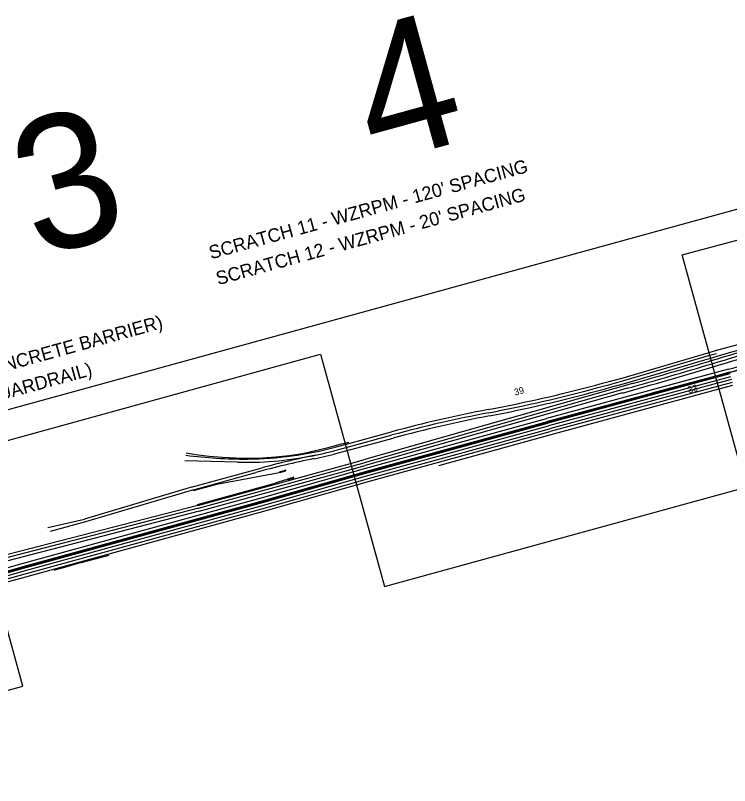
# Model space of a CAD drawing. Extents: x 2129512 to 2138277, y 657615 to 661243.
# Drawn here: x 2132183 to 2134849, y 657615 to 660491 of the extents above; entities that cross this region are included whole.
import ezdxf

# ---------------------------------------------------------------- set-up
doc = ezdxf.new("R2010")
doc.units = 0
for name, color, linetype in [('GE_X_Alignment_100_Stations', 7, 'Continuous'), ('MT_P_CL_50', 7, 'Continuous'), ('MT_P_Dotted_Line', 7, 'Continuous'), ('MT_P_Gore_Marking', 7, 'Continuous'), ('MT_P_PCB', 7, 'Continuous'), ('MT_P_Temp_Road', 7, 'Continuous'), ('MT_P_Traffic_Attenuator', 7, 'Continuous'), ('MT_P_Work_Area', 7, 'Continuous'), ('MT_X_Dotted_Line', 7, 'Continuous'), ('MT_X_Drums', 7, 'Continuous'), ('MT_X_Gore_Marking', 7, 'Continuous'), ('MT_X_Traffic_Attenuator', 7, 'Continuous'), ('PV_P_Shoulder', 7, 'Continuous'), ('SC_Scratch1', 7, 'Continuous')]:
    doc.layers.add(name, color=color, linetype=linetype)

msp = doc.modelspace()

# ---------------------------------------------------------------- linework, layer by layer
at = {"layer": 'GE_X_Alignment_100_Stations'}
for p, q in [((2134796.6, 659239.6), (2135219, 659355.8)), ((2134451.1, 659138.2), (2134772.2, 659232.4)), ((2134772.2, 659232.4), (2134796.6, 659239.6)), ((2134399, 659123.9), (2134451.1, 659138.2))]:
    msp.add_line(p, q, dxfattribs=at)
msp.add_arc((2132878.5, 664648.1), 5729.6, 281.30004, 285.38861, dxfattribs=at)
at = {"layer": 'MT_P_CL_50'}
for p, q in [((2134456.9, 659117), (2134778.1, 659211.2)), ((2134778.1, 659211.2), (2134802.4, 659218.3)), ((2134855.4, 659131.3), (2134803.9, 659117.4)), ((2134803.9, 659117.4), (2134176.4, 658947.7)), ((2134806.8, 659106.8), (2134179.4, 658937.1)), ((2134858.3, 659120.7), (2134806.8, 659106.8)), ((2133501.5, 658761.9), (2134176.4, 658947.7)), ((2133504.4, 658751.3), (2134179.4, 658937.1)), ((2133453.4, 658748.3), (2133501.5, 658761.9)), ((2133116.7, 658652.7), (2133453.4, 658748.3)), ((2132219.5, 658405.8), (2133116.7, 658652.7))]:
    msp.add_line(p, q, dxfattribs=at)
at = {"layer": 'MT_P_Dotted_Line'}
for p, q in [((2134793.3, 659155.9), (2134555.2, 659091.6)), ((2134844.8, 659169.9), (2134793.3, 659155.9)), ((2134847.9, 659158.3), (2134796.5, 659144.4)), ((2134796.5, 659144.4), (2134558.4, 659080)), ((2132863.9, 658661.3), (2133434.2, 658818.3)), ((2133434.2, 658818.3), (2133482.4, 658831.5)), ((2133437.1, 658807.6), (2133485.4, 658820.9)), ((2133440, 658797), (2133488.4, 658810.4)), ((2132866.7, 658650.7), (2133437.1, 658807.6)), ((2132869.6, 658640), (2133440, 658797)), ((2132863.9, 658661.3), (2132080.8, 658459.6)), ((2132866.7, 658650.7), (2132083.8, 658448.9)), ((2132869.6, 658640), (2132086.9, 658437.4))]:
    msp.add_line(p, q, dxfattribs=at)
for radius, start in [(2286, 285.1339), (2298, 285.1338)]:
    msp.add_arc((2134248, 661376.6), radius, start, 291.781, dxfattribs=at)
at = {"layer": 'MT_P_Gore_Marking'}
for p, q in [((2133413.3, 658894.2), (2133427.3, 658897.8)), ((2132935.2, 658741), (2133161.2, 658783.4)), ((2133161.2, 658783.4), (2133170.9, 658786)), ((2133191.1, 658756.8), (2133152.6, 658743.9)), ((2133191.1, 658756.8), (2133200.7, 658759.4)), ((2132848.4, 658717.1), (2132935.2, 658741)), ((2132863.1, 658664.2), (2133152.6, 658743.9)), ((2132429.1, 658447.5), (2132533.2, 658476.1))]:
    msp.add_line(p, q, dxfattribs=at)
for points in [[(2132820.8, 658857.2), (2132856.8, 658851.4), (2132907.1, 658845.2), (2132956.8, 658841), (2133006, 658838.4), (2133060.1, 658838.1), (2133105.4, 658839.2), (2133155.2, 658842.8), (2133204.8, 658847.5), (2133254.8, 658855.7), (2133303.6, 658866.6), (2133350.5, 658877.8), (2133400.2, 658890.8), (2133413.3, 658894.2)], [(2132429.1, 658447.5), (2132366.6, 658429.8), (2132329.4, 658418.9), (2132327.6, 658418.7)]]:
    msp.add_lwpolyline(points, dxfattribs=at)
at = {"layer": 'MT_P_PCB'}
for p, q in [((2134793.3, 659155.9), (2134165.8, 658986.2)), ((2134844.8, 659169.9), (2134793.3, 659155.9)), ((2134847.9, 659158.3), (2134796.5, 659144.4)), ((2134796.5, 659144.4), (2134169, 658974.7)), ((2134798.1, 659138.6), (2134170.6, 658968.9)), ((2134849.5, 659152.5), (2134798.1, 659138.6)), ((2134486.3, 659116.4), (2133482.4, 658831.5)), ((2134182.5, 658925.5), (2134809.8, 659096.1)), ((2134809.8, 659096.1), (2134861.2, 659110.1)), ((2134449.7, 659081.1), (2133488.4, 658810.4)), ((2133490.9, 658800.5), (2134165.8, 658986.2)), ((2133494.1, 658788.9), (2134169, 658974.7)), ((2133495.7, 658783.1), (2134170.6, 658968.9)), ((2133414.6, 658889.2), (2133586.7, 658936)), ((2133764.1, 658810.3), (2134182.5, 658925.5)), ((2133421, 658866.1), (2133593, 658912.8)), ((2133377.3, 658879.1), (2133414.6, 658889.2)), ((2133383.6, 658855.9), (2133421, 658866.1)), ((2133011.8, 658822.7), (2132815.6, 658827.2)), ((2132863.9, 658661.3), (2133434.2, 658818.3)), ((2133434.2, 658818.3), (2133482.4, 658831.5)), ((2133440, 658797), (2133488.4, 658810.4)), ((2132844.6, 658730.6), (2133104.1, 658802)), ((2132847.6, 658720), (2133080.6, 658784.1)), ((2132869.6, 658640), (2133440, 658797)), ((2133106.1, 658691.3), (2133442.8, 658786.8)), ((2133442.8, 658786.8), (2133490.9, 658800.5)), ((2133446, 658775.3), (2133494.1, 658788.9)), ((2133447.6, 658769.5), (2133495.7, 658783.1)), ((2133109.3, 658679.7), (2133446, 658775.3)), ((2133110.9, 658674), (2133447.6, 658769.5)), ((2133456.3, 658737.7), (2133504.4, 658751.3)), ((2132844.6, 658730.6), (2132441.7, 658610)), ((2133119.6, 658642.1), (2133456.3, 658737.7)), ((2132847.6, 658720), (2132444.9, 658599.5)), ((2132208.9, 658444.4), (2133106.1, 658691.3)), ((2132212, 658432.8), (2133109.3, 658679.7)), ((2132213.6, 658427), (2133110.9, 658674)), ((2132863.9, 658661.3), (2132080.8, 658459.6)), ((2132869.6, 658640), (2132086.9, 658437.4)), ((2132222.4, 658395.2), (2133119.6, 658642.1)), ((2132304.3, 658578.4), (2132441.7, 658610)), ((2132444.9, 658599.5), (2132312.6, 658564.1)), ((2132093.8, 658412.5), (2132208.9, 658444.4)), ((2132097, 658400.9), (2132212, 658432.8)), ((2132098.6, 658395.2), (2132213.6, 658427)), ((2132107.3, 658363.3), (2132222.4, 658395.2))]:
    msp.add_line(p, q, dxfattribs=at)
for centre, radius, start, end in [((2128236.9, 681140.9), 22918, 286.60693, 287.56698), ((2134248, 661376.6), 2286, 285.1339, 291.781), ((2134248, 661376.6), 2298, 285.1338, 291.781), ((2128236.9, 681140.9), 22918, 285.72897, 286.60693), ((2134842.9, 654308.7), 4794.7, 100.7572, 105.1883), ((2132878.5, 664648.1), 5729.6, 280.75722, 281.2999), ((2134842.9, 654308.7), 4770.7, 100.7572, 105.1883), ((2132878.5, 664648.1), 5753.6, 280.75722, 281.2999), ((2133041.6, 660115.8), 1281.5, 270.3665, 285.1883), ((2133039, 660522.9), 1688.5, 262.5293, 270.3665), ((2133041.6, 660115.8), 1305.5, 281.3395, 285.1883), ((2133041.6, 660115.8), 1293.5, 268.6795, 272.3466), ((2133921, 655730.4), 3167.3, 101.3395, 105.3886)]:
    msp.add_arc(centre, radius, start, end, dxfattribs=at)
at = {"layer": 'MT_P_Temp_Road'}
for p, q in [((2134848.7, 659155.4), (2134797.3, 659141.5)), ((2134797.3, 659141.5), (2134169.8, 658971.8)), ((2133494.9, 658786), (2134169.8, 658971.8)), ((2132935.2, 658741), (2133161.2, 658783.4)), ((2133161.2, 658783.4), (2133170.9, 658786)), ((2133446.8, 658772.4), (2133494.9, 658786)), ((2133110.1, 658676.8), (2133446.8, 658772.4)), ((2133191.1, 658756.8), (2133152.6, 658743.9)), ((2133191.1, 658756.8), (2133200.7, 658759.4)), ((2132848.4, 658717.1), (2132935.2, 658741)), ((2132863.1, 658664.2), (2133152.6, 658743.9)), ((2132212.8, 658429.9), (2133110.1, 658676.8)), ((2132097.8, 658398), (2132212.8, 658429.9))]:
    msp.add_line(p, q, dxfattribs=at)
at = {"layer": 'MT_P_Work_Area'}
for p, q in [((2134802.4, 659218.3), (2135222, 659345.2)), ((2134454, 659127.6), (2134775.2, 659221.8)), ((2134775.2, 659221.8), (2134799.5, 659228.9)), ((2134801, 659128), (2134173.5, 658958.3)), ((2134401.9, 659113.3), (2134454, 659127.6)), ((2134852.5, 659141.9), (2134801, 659128)), ((2134468.3, 659098.8), (2133485.4, 658820.9)), ((2134404.8, 659102.7), (2134456.9, 659117)), ((2133498.6, 658772.5), (2134173.5, 658958.3)), ((2133417.8, 658877.7), (2133589.9, 658924.4)), ((2133380.5, 658867.5), (2133417.8, 658877.7)), ((2133437.1, 658807.6), (2133485.4, 658820.9)), ((2132866.7, 658650.7), (2133437.1, 658807.6)), ((2133113.8, 658663.3), (2133450.5, 658758.9)), ((2133450.5, 658758.9), (2133498.6, 658772.5)), ((2132866.7, 658650.7), (2132083.8, 658448.9)), ((2132216.5, 658416.4), (2133113.8, 658663.3)), ((2132101.5, 658384.5), (2132216.5, 658416.4)), ((2132104.4, 658373.9), (2132219.5, 658405.8))]:
    msp.add_line(p, q, dxfattribs=at)
for centre, radius, start, end in [((2128236.9, 681140.9), 22894, 286.60821, 287.56698), ((2128236.9, 681140.9), 22906, 286.60757, 287.56698), ((2128236.9, 681140.9), 22906, 285.78568, 286.60757), ((2128236.9, 681140.9), 22894, 285.84115, 286.60821), ((2132864.9, 664644.8), 5741.1, 281.43983, 285.52842), ((2132851.3, 664641.5), 5752.6, 281.57905, 285.66766), ((2132878.5, 664648.1), 5741.6, 280.75722, 281.2999), ((2134842.9, 654308.7), 4782.7, 100.7572, 105.1883), ((2133041.6, 660115.8), 1293.5, 272.3466, 285.1883), ((2134037.8, 655306.2), 3618.2, 101.7019, 104.9537)]:
    msp.add_arc(centre, radius, start, end, dxfattribs=at)
at = {"layer": 'MT_X_Dotted_Line'}
for p, q in [((2134848.7, 659155.4), (2134797.3, 659141.5)), ((2134797.3, 659141.5), (2134169.8, 658971.8)), ((2133494.9, 658786), (2134169.8, 658971.8)), ((2133446.8, 658772.4), (2133494.9, 658786)), ((2133110.1, 658676.8), (2133446.8, 658772.4)), ((2132212.8, 658429.9), (2133110.1, 658676.8)), ((2132097.8, 658398), (2132212.8, 658429.9))]:
    msp.add_line(p, q, dxfattribs=at)
at = {"layer": 'MT_X_Drums'}
msp.add_line((2133413.3, 658894.2), (2133427.3, 658897.8), dxfattribs=at)
for points in [[(2132820.8, 658857.2), (2132856.8, 658851.4), (2132907.1, 658845.2), (2132956.8, 658841), (2133006, 658838.4), (2133060.1, 658838.1), (2133105.4, 658839.2), (2133155.2, 658842.8), (2133204.8, 658847.5), (2133254.8, 658855.7), (2133303.6, 658866.6), (2133350.5, 658877.8), (2133400.2, 658890.8), (2133413.3, 658894.2)], [(2132429.1, 658447.5), (2132366.6, 658429.8), (2132329.4, 658418.9), (2132327.6, 658418.7)]]:
    msp.add_lwpolyline(points, dxfattribs=at)
at = {"layer": 'MT_X_Gore_Marking'}
for p, q in [((2134848.2, 659157.3), (2134796.7, 659143.4)), ((2134848.2, 659157.3), (2134917.3, 659176.3)), ((2134796.7, 659143.4), (2134169.3, 658973.7)), ((2134797.8, 659139.5), (2134170.3, 658969.9)), ((2134849.3, 659153.5), (2134797.8, 659139.5)), ((2133494.4, 658788), (2134169.3, 658973.7)), ((2133495.4, 658784.1), (2134170.3, 658969.9)), ((2132935.2, 658741), (2133161.2, 658783.4)), ((2133161.2, 658783.4), (2133170.9, 658786)), ((2133446.3, 658774.3), (2133494.3, 658788)), ((2133447.3, 658770.5), (2133495.4, 658784.1)), ((2133109.5, 658678.8), (2133446.3, 658774.3)), ((2133110.6, 658674.9), (2133447.3, 658770.5)), ((2133191.1, 658756.8), (2133152.6, 658743.9)), ((2133191.1, 658756.8), (2133200.7, 658759.4)), ((2132848.4, 658717.1), (2132935.2, 658741)), ((2132863.1, 658664.2), (2133152.6, 658743.9)), ((2132212.3, 658431.8), (2133109.5, 658678.8)), ((2132213.4, 658428), (2133110.6, 658674.9)), ((2132429.1, 658447.5), (2132533.2, 658476.1)), ((2132097.2, 658400), (2132212.3, 658431.8)), ((2132098.3, 658396.1), (2132213.4, 658428))]:
    msp.add_line(p, q, dxfattribs=at)
at = {"layer": 'MT_X_Traffic_Attenuator'}
for p, q in [((2134454, 659127.6), (2134775.2, 659221.8)), ((2134775.2, 659221.8), (2134799.5, 659228.9)), ((2134401.9, 659113.3), (2134454, 659127.6)), ((2134468.3, 659098.8), (2133485.4, 658820.9)), ((2133417.8, 658877.7), (2133589.9, 658924.4)), ((2133380.5, 658867.5), (2133417.8, 658877.7))]:
    msp.add_line(p, q, dxfattribs=at)
for centre, radius, start, end in [((2128236.9, 681140.9), 22906, 286.60757, 287.56698), ((2128236.9, 681140.9), 22906, 285.78568, 286.60757), ((2132864.9, 664644.8), 5741.1, 281.43983, 285.52842), ((2132878.5, 664648.1), 5741.6, 280.75722, 281.2999), ((2134842.9, 654308.7), 4782.7, 100.7572, 105.1883)]:
    msp.add_arc(centre, radius, start, end, dxfattribs=at)
at = {"layer": 'PV_P_Shoulder'}
msp.add_lwpolyline([(2134910.7, 658729.4), (2134671.9, 659597.2), (2136054.1, 659967.1), (2136234.4, 659083.8), (2137570.2, 659277.9), (2137491.7, 660175.9), (2137412.1, 660465.2), (2130593.3, 658588.4), (2130861.2, 657615), (2132211, 657986.5), (2131972.2, 658854.2), (2133322, 659225.7), (2133560.8, 658358)], close=True, dxfattribs=at)
at = {"layer": 'SC_Scratch1'}
for p, q in [((2133170.5, 658787.3), (2133191.3, 658793)), ((2133171.2, 658784.8), (2133170.5, 658787.3)), ((2133171.2, 658784.8), (2133191.9, 658790.5)), ((2133171.3, 658787.5), (2133172.9, 658785.3)), ((2133172.2, 658787.7), (2133172, 658785.1)), ((2133173.1, 658787.9), (2133174.6, 658785.8)), ((2133173.9, 658788.2), (2133173.7, 658785.5)), ((2133174.8, 658788.4), (2133176.3, 658786.3)), ((2133175.7, 658788.7), (2133175.5, 658786)), ((2133176.5, 658788.9), (2133178.1, 658786.7)), ((2133177.4, 658789.1), (2133177.2, 658786.5)), ((2133178.3, 658789.4), (2133179.8, 658787.2)), ((2133179.1, 658789.6), (2133178.9, 658787)), ((2133180, 658789.9), (2133181.5, 658787.7)), ((2133180.9, 658790.1), (2133180.7, 658787.4)), ((2133181.7, 658790.3), (2133183.3, 658788.2)), ((2133182.6, 658790.6), (2133182.4, 658787.9)), ((2133183.5, 658790.8), (2133185, 658788.6)), ((2133184.3, 658791), (2133184.1, 658788.4)), ((2133185.2, 658791.3), (2133186.7, 658789.1)), ((2133186.1, 658791.5), (2133185.9, 658788.9)), ((2133186.9, 658791.8), (2133188.5, 658789.6)), ((2133187.8, 658792), (2133187.6, 658789.4)), ((2133188.7, 658792.2), (2133190.2, 658790.1)), ((2133189.5, 658792.5), (2133189.3, 658789.8)), ((2133190.4, 658792.7), (2133191.9, 658790.5)), ((2133191.3, 658793), (2133191.1, 658790.3)), ((2133200.4, 658760.6), (2133221.1, 658766.3)), ((2133201, 658758.2), (2133200.4, 658760.6)), ((2133201, 658758.2), (2133221.8, 658763.9)), ((2133201.2, 658760.9), (2133202.7, 658758.7)), ((2133202, 658761.1), (2133201.8, 658758.5)), ((2133202.9, 658761.3), (2133204.4, 658759.2)), ((2133203.8, 658761.6), (2133203.6, 658758.9)), ((2133204.6, 658761.8), (2133206.2, 658759.6)), ((2133205.5, 658762.1), (2133205.3, 658759.4)), ((2133206.4, 658762.3), (2133207.9, 658760.1)), ((2133207.2, 658762.5), (2133207, 658759.9)), ((2133208.1, 658762.8), (2133209.6, 658760.6)), ((2133209, 658763), (2133208.8, 658760.4)), ((2133209.8, 658763.2), (2133211.4, 658761.1)), ((2133210.7, 658763.5), (2133210.5, 658760.8)), ((2133211.6, 658763.7), (2133213.1, 658761.6)), ((2133212.4, 658764), (2133212.2, 658761.3)), ((2133213.3, 658764.2), (2133214.8, 658762)), ((2133214.2, 658764.4), (2133214, 658761.8)), ((2133215, 658764.7), (2133216.6, 658762.5)), ((2133215.9, 658764.9), (2133215.7, 658762.3)), ((2133216.8, 658765.2), (2133218.3, 658763)), ((2133217.6, 658765.4), (2133217.4, 658762.7)), ((2133218.5, 658765.6), (2133220, 658763.5)), ((2133219.4, 658765.9), (2133219.2, 658763.2)), ((2133220.2, 658766.1), (2133221.8, 658763.9)), ((2133221.1, 658766.3), (2133220.9, 658763.7))]:
    msp.add_line(p, q, dxfattribs=at)
for centre in [(2133191.6, 658791.8), (2133221.4, 658765.1)]:
    msp.add_arc(centre, 1.25, 285.3886, 105.3886, dxfattribs=at)

# ---------------------------------------------------------------- texts
at = {"layer": 'MT_P_Dotted_Line'}
for s, height, p in [("SCRATCH 12 - WZRPM - 20' SPACING", 50, (2132939.9, 659483.6)), ('33', 25, (2134696.2, 659079.9))]:
    msp.add_text(s, height=height, rotation=15.3886, dxfattribs=at).set_placement(p)
at = {"layer": 'MT_P_Traffic_Attenuator'}
for s, p in [('4', (2133524.7, 659932.8)), ('3', (2132261.7, 659585.1))]:
    msp.add_text(s, height=500, rotation=15.3872, dxfattribs=at).set_placement(p)
at = {"layer": 'MT_X_Drums'}
msp.add_text('SCRATCH 16 - BARRIER REFLECTORS, TYPE 2 (GUARDRAIL)', height=50, rotation=15.3886, dxfattribs=at).set_placement((2130582.6, 658627.4))
at = {"layer": 'MT_X_Gore_Marking'}
msp.add_text('SCRATCH 15 - BARRIER REFLECTORS, TYPE 1 (CONCRETE BARRIER)', height=50, rotation=15.3886, dxfattribs=at).set_placement((2130556.1, 658723.8))
at = {"layer": 'MT_X_Traffic_Attenuator'}
for s, height, p in [("SCRATCH 11 - WZRPM - 120' SPACING", 50, (2132913.4, 659580)), ('39', 25, (2134048.3, 659071))]:
    msp.add_text(s, height=height, rotation=15.3886, dxfattribs=at).set_placement(p)

doc.saveas('drawing.dxf')
